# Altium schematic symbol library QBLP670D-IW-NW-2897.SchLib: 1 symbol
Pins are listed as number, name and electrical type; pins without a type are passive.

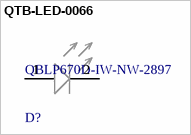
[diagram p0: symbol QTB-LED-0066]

## QTB-LED-0066
designator D?, comment QBLP670D-IW-NW-2897
LED NEUTRAL WHITE CLEAR 2PLCC SMD; Manufacturer: QT Brightek (QTB); Lens Size: 2.4mm; Luminous Intensity: 9500mcd; Test Current: 20mA; Lens Color: Colorless; Lens Style: Round with Domed Top; Forward Voltage: 2.8V; Viewing Angle: 30°
footprint QBLP670D-IW-NW-2897-MFG
pins: 1 ANODE (+), 2 CATHODE (-)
